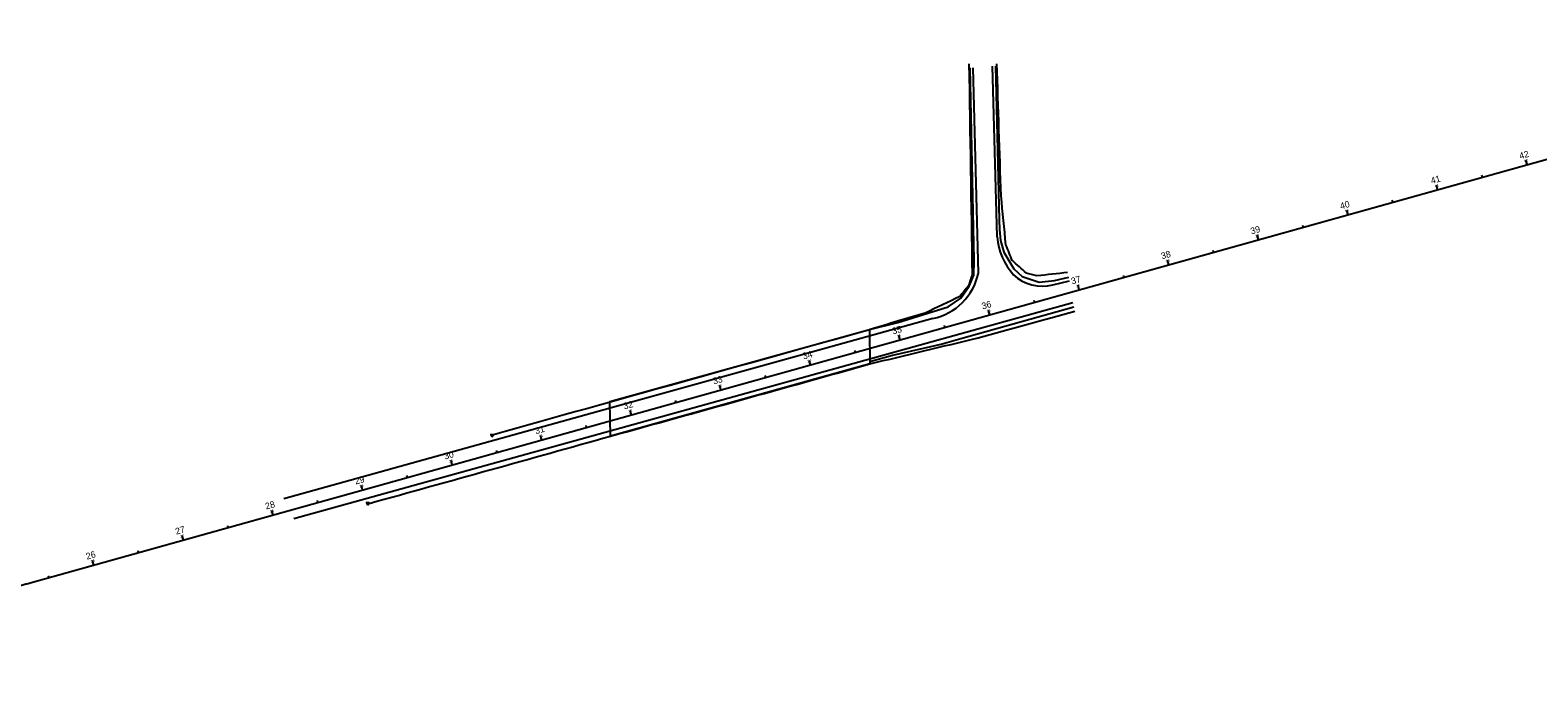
# Model space of a CAD drawing. Extents: x 1512289 to 1610162, y 552531 to 645498.
# Drawn here: x 1541212 to 1542833, y 586720 to 587419 of the extents above; entities that cross this region are included whole.
import ezdxf

# ---------------------------------------------------------------- set-up
doc = ezdxf.new("R2010")
doc.units = 0
for name, color, linetype in [('BR_X_SV_Deck_Top', 7, 'Continuous'), ('GE_X_CL_20', 7, 'Continuous'), ('GE_X_CL_50', 7, 'Continuous'), ('GK_Visualization', 7, 'Continuous'), ('MT_P_CL_Double_Solid', 7, 'Continuous'), ('PV_X_EOP', 7, 'Continuous'), ('PV_X_Shoulder', 7, 'Continuous'), ('RD_X_Anchor_Assembly', 7, 'Continuous'), ('RD_X_GR_Lt', 7, 'Continuous'), ('RD_X_GR_Rt', 7, 'Continuous')]:
    doc.layers.add(name, color=color, linetype=linetype)

msp = doc.modelspace()

# ---------------------------------------------------------------- linework, layer by layer
at = {"layer": 'BR_X_SV_Deck_Top'}
msp.add_lwpolyline([(1541836.1, 586981.9), (1541835.6, 587019.2), (1542114.7, 587096.4), (1542114.9, 587059.6)], close=True, dxfattribs=at)
at = {"layer": 'GE_X_CL_20'}
for p, q in [((1541212.2, 586824.2), (1543339.3, 587418.5)), ((1542821.7, 587273.9), (1542821.2, 587275.8)), ((1542773.6, 587260.4), (1542773, 587262.4)), ((1542725.4, 587247), (1542724.9, 587248.9)), ((1542677.3, 587233.5), (1542676.7, 587235.5)), ((1542581, 587206.6), (1542580.4, 587208.5)), ((1542629.1, 587220.1), (1542628.6, 587222)), ((1542532.8, 587193.2), (1542532.3, 587195.1)), ((1542484.6, 587179.7), (1542484.1, 587181.6)), ((1542436.5, 587166.2), (1542435.9, 587168.2)), ((1542388.3, 587152.8), (1542387.8, 587154.7)), ((1542292, 587125.9), (1542291.5, 587127.8)), ((1542340.2, 587139.3), (1542339.6, 587141.3)), ((1542243.9, 587112.4), (1542243.3, 587114.4)), ((1542195.7, 587099), (1542195.2, 587100.9)), ((1542147.6, 587085.5), (1542147, 587087.4)), ((1542099.4, 587072.1), (1542098.9, 587074)), ((1542003.1, 587045.2), (1542002.5, 587047.1)), ((1542051.2, 587058.6), (1542050.7, 587060.5)), ((1541954.9, 587031.7), (1541954.4, 587033.6)), ((1541906.8, 587018.2), (1541906.2, 587020.2)), ((1541858.6, 587004.8), (1541858.1, 587006.7)), ((1541810.5, 586991.3), (1541809.9, 586993.3)), ((1541714.2, 586964.4), (1541713.6, 586966.3)), ((1541762.3, 586977.9), (1541761.8, 586979.8)), ((1541666, 586951), (1541665.5, 586952.9)), ((1541617.8, 586937.5), (1541617.3, 586939.4)), ((1541569.7, 586924.1), (1541569.1, 586926)), ((1541521.5, 586910.6), (1541521, 586912.5)), ((1541425.2, 586883.7), (1541424.7, 586885.6)), ((1541473.4, 586897.1), (1541472.8, 586899.1)), ((1541377.1, 586870.2), (1541376.5, 586872.2)), ((1541328.9, 586856.8), (1541328.4, 586858.7)), ((1541280.8, 586843.3), (1541280.2, 586845.2)), ((1541232.6, 586829.9), (1541232.1, 586831.8))]:
    msp.add_line(p, q, dxfattribs=at)
at = {"layer": 'GE_X_CL_50'}
for p, q in [((1541212.2, 586824.2), (1543339.3, 587418.5)), ((1542821.7, 587273.9), (1542820.4, 587278.7)), ((1542725.4, 587247), (1542724.1, 587251.8)), ((1542629.1, 587220.1), (1542627.8, 587224.9)), ((1542532.8, 587193.2), (1542531.5, 587198)), ((1542436.5, 587166.2), (1542435.1, 587171.1)), ((1542340.2, 587139.3), (1542338.8, 587144.2)), ((1542243.9, 587112.4), (1542242.5, 587117.2)), ((1542147.6, 587085.5), (1542146.2, 587090.3)), ((1542051.2, 587058.6), (1542049.9, 587063.4)), ((1541954.9, 587031.7), (1541953.6, 587036.5)), ((1541858.6, 587004.8), (1541857.3, 587009.6)), ((1541762.3, 586977.9), (1541761, 586982.7)), ((1541666, 586951), (1541664.7, 586955.8)), ((1541569.7, 586924.1), (1541568.3, 586928.9)), ((1541473.4, 586897.1), (1541472, 586902)), ((1541377.1, 586870.2), (1541375.7, 586875)), ((1541280.8, 586843.3), (1541279.4, 586848.1))]:
    msp.add_line(p, q, dxfattribs=at)
at = {"layer": 'GK_Visualization'}
for p, q in [((1541212.2, 586824.2), (1543339.3, 587418.5)), ((1541212.2, 586824.3), (1541212.2, 586824.1)), ((1541212.3, 586824.2), (1541212.2, 586824.2))]:
    msp.add_line(p, q, dxfattribs=at)
msp.add_spline([(1540878.3, 586719.8), (1540882.7, 586721.5), (1540887.2, 586723.1), (1540891.6, 586724.8), (1540896, 586726.4), (1540900.5, 586728.1), (1540904.9, 586729.7), (1540909.4, 586731.3), (1540913.8, 586732.9), (1540918.3, 586734.5), (1540922.7, 586736.1), (1540927.2, 586737.7), (1540931.6, 586739.2), (1540936.1, 586740.8), (1540940.6, 586742.4), (1540945, 586743.9), (1540949.5, 586745.4), (1540954, 586746.9), (1540958.5, 586748.5), (1540963, 586750), (1540967.4, 586751.5), (1540971.9, 586753), (1540976.4, 586754.4), (1540980.9, 586755.9), (1540985.4, 586757.4), (1540989.9, 586758.8), (1540994.4, 586760.3), (1540998.9, 586761.7), (1541003.4, 586763.2), (1541007.9, 586764.6), (1541012.4, 586766), (1541017, 586767.4), (1541021.5, 586768.8), (1541026, 586770.2), (1541030.5, 586771.6), (1541035, 586773), (1541039.5, 586774.4), (1541044.1, 586775.8), (1541048.6, 586777.2), (1541053.1, 586778.5), (1541057.7, 586779.9), (1541062.2, 586781.3), (1541066.7, 586782.6), (1541071.3, 586784), (1541075.8, 586785.3), (1541080.3, 586786.7), (1541084.9, 586788), (1541089.4, 586789.3), (1541093.9, 586790.6), (1541098.5, 586792), (1541103, 586793.3), (1541107.6, 586794.6), (1541112.1, 586795.9), (1541116.7, 586797.2), (1541121.2, 586798.5), (1541125.7, 586799.8), (1541130.3, 586801.1), (1541134.8, 586802.4), (1541139.4, 586803.7), (1541143.9, 586805), (1541148.5, 586806.3), (1541153, 586807.6), (1541157.6, 586808.9), (1541162.1, 586810.1), (1541166.7, 586811.4), (1541171.3, 586812.7), (1541175.8, 586814), (1541180.4, 586815.3), (1541184.9, 586816.5), (1541189.5, 586817.8), (1541194, 586819.1), (1541198.6, 586820.4), (1541203.1, 586821.6), (1541207.7, 586822.9), (1541212.2, 586824.2)], degree=3, dxfattribs=at)
msp.add_spline([(1540878.3, 586719.8), (1540882.7, 586721.5), (1540887.2, 586723.1), (1540891.6, 586724.8), (1540896, 586726.4), (1540900.5, 586728.1), (1540904.9, 586729.7), (1540909.4, 586731.3), (1540913.8, 586732.9), (1540918.3, 586734.5), (1540922.7, 586736.1), (1540927.2, 586737.7), (1540931.6, 586739.2), (1540936.1, 586740.8), (1540940.6, 586742.4), (1540945, 586743.9), (1540949.5, 586745.4), (1540954, 586746.9), (1540958.5, 586748.5), (1540963, 586750), (1540967.4, 586751.5), (1540971.9, 586753), (1540976.4, 586754.4), (1540980.9, 586755.9), (1540985.4, 586757.4), (1540989.9, 586758.8), (1540994.4, 586760.3), (1540998.9, 586761.7), (1541003.4, 586763.2), (1541007.9, 586764.6), (1541012.4, 586766), (1541017, 586767.4), (1541021.5, 586768.8), (1541026, 586770.2), (1541030.5, 586771.6), (1541035, 586773), (1541039.5, 586774.4), (1541044.1, 586775.8), (1541048.6, 586777.2), (1541053.1, 586778.5), (1541057.7, 586779.9), (1541062.2, 586781.3), (1541066.7, 586782.6), (1541071.3, 586784), (1541075.8, 586785.3), (1541080.3, 586786.7), (1541084.9, 586788), (1541089.4, 586789.3), (1541093.9, 586790.6), (1541098.5, 586792), (1541103, 586793.3), (1541107.6, 586794.6), (1541112.1, 586795.9), (1541116.7, 586797.2), (1541121.2, 586798.5), (1541125.7, 586799.8), (1541130.3, 586801.1), (1541134.8, 586802.4), (1541139.4, 586803.7), (1541143.9, 586805), (1541148.5, 586806.3), (1541153, 586807.6), (1541157.6, 586808.9), (1541162.1, 586810.1), (1541166.7, 586811.4), (1541171.3, 586812.7), (1541175.8, 586814), (1541180.4, 586815.3), (1541184.9, 586816.5), (1541189.5, 586817.8), (1541194, 586819.1), (1541198.6, 586820.4), (1541203.1, 586821.6), (1541207.7, 586822.9), (1541212.2, 586824.2)], degree=3, dxfattribs=at)
at = {"layer": 'MT_P_CL_Double_Solid'}
msp.add_line((1542364.3, 587146), (1542845.8, 587280.6), dxfattribs=at)
at = {"layer": 'PV_X_EOP'}
for p, q in [((1542231.7, 587157.2), (1542226.2, 587378)), ((1542251.7, 587196.1), (1542246.8, 587379.6)), ((1542311.7, 587144.7), (1542329.7, 587148.8)), ((1542333.3, 587125.1), (1541495.6, 586892.8)), ((1542182.7, 587108.4), (1541484.8, 586914.4))]:
    msp.add_line(p, q, dxfattribs=at)
for centre, radius, start, end in [((1542320.3, 587201.9), 68.8, 184.8254, 222.4062), ((1542170.5, 587169.7), 62.4, 281.2139, 348.4506), ((1542300.1, 587187.5), 44.3, 226.2053, 285.2475)]:
    msp.add_arc(centre, radius, start, end, dxfattribs=at)
at = {"layer": 'PV_X_Shoulder'}
for points in [[(1542114.7, 587096.4), (1542145.1, 587104.2), (1542199.3, 587120.8), (1542212.9, 587130.4), (1542221.9, 587143.3), (1542226.7, 587155), (1542227.2, 587171), (1542222.7, 587378)], [(1542250.2, 587379.6), (1542254.2, 587214.6), (1542254.5, 587204), (1542255.4, 587192.2), (1542259, 587179.6), (1542269.9, 587161.7), (1542278.8, 587153.7), (1542297.2, 587147.4), (1542313.5, 587149.3), (1542329, 587152.7)], [(1542334.3, 587120.6), (1542212.7, 587086.7), (1542192.6, 587080.9), (1542139.5, 587068.5), (1542114.9, 587061.9)]]:
    msp.add_lwpolyline(points, dxfattribs=at)
at = {"layer": 'RD_X_Anchor_Assembly'}
for points in [[(1541708.7, 586981.2), (1541710.5, 586983.4), (1541707.6, 586983.8)], [(1541575, 586907.8), (1541576.7, 586910.1), (1541573.9, 586910.4)]]:
    msp.add_lwpolyline(points, close=True, dxfattribs=at)
at = {"layer": 'RD_X_GR_Lt'}
for centre, radius, start, end in [((1534235.2, 616124), 30117.3, 285.39663, 285.60221), ((1534361.7, 619537.7), 33390.7, 283.42641, 283.63199), ((1520328.7, 664721.2), 80659.6, 285.464626, 285.670205), ((1521573.7, 659217.2), 75023.4, 285.463483, 285.669062)]:
    msp.add_arc(centre, radius, start, end, dxfattribs=at)
at = {"layer": 'RD_X_GR_Rt'}
for centre, radius, start, end in [((3234596.3, 612398.8), 1692559.6, 180.8468843, 180.8545504), ((479730.9, 553586.9), 1063058, 1.8141208, 1.8217869), ((1149971.9, 548704), 394172.5, 5.602802, 5.610468), ((1414393.2, 536043.9), 137716.9, 21.792409, 21.800075), ((1442496, 474076.2), 150813.9, 48.573508, 48.581174), ((1627381, 517588.8), 109954.8, 140.759703, 140.76737), ((1633808, 557735.3), 96192.6, 162.190728, 162.198394), ((1519007.3, 501908), 88369.7, 74.720867, 74.728533), ((1569928.3, 341509.6), 247194, 96.410799, 96.418465), ((1675563.6, 307707.1), 309614.3, 115.512201, 115.519867), ((1673944.7, 145678.3), 460683.3, 106.620573, 106.628239), ((1825870.5, -430626.2), 1056539.8, 105.5791754, 105.6020033)]:
    msp.add_arc(centre, radius, start, end, dxfattribs=at)

# ---------------------------------------------------------------- texts
at = {"layer": 'GE_X_CL_20'}
for s, p in [('42', (1542818.7, 587276.2)), ('41', (1542722.9, 587249.4)), ('40', (1542626, 587222.3)), ('39', (1542529.8, 587195.4)), ('38', (1542433.5, 587168.5)), ('37', (1542337.1, 587141.6)), ('36', (1542240.8, 587114.7)), ('35', (1542144.5, 587087.8)), ('34', (1542048.2, 587060.9)), ('33', (1541951.9, 587034)), ('32', (1541855.6, 587007.1)), ('31', (1541759.8, 586980.3)), ('30', (1541662.9, 586953.2)), ('29', (1541566.7, 586926.3)), ('28', (1541470.4, 586899.4)), ('27', (1541374, 586872.5)), ('26', (1541277.8, 586845.6))]:
    msp.add_text(s, height=2.8, rotation=15.6111, dxfattribs=at).set_placement(p)
at = {"layer": 'GE_X_CL_50'}
for s, p in [('42', (1542814.2, 587279.6)), ('41', (1542719.1, 587253)), ('40', (1542621.5, 587225.7)), ('39', (1542525.3, 587198.8)), ('38', (1542429.1, 587172)), ('37', (1542332.4, 587145)), ('36', (1542236.3, 587118.1)), ('35', (1542140, 587091.2)), ('34', (1542043.8, 587064.3)), ('33', (1541947.3, 587037.4)), ('32', (1541851.1, 587010.5)), ('31', (1541755.9, 586983.9)), ('30', (1541658.3, 586956.6)), ('29', (1541562.3, 586929.8)), ('28', (1541466, 586902.9)), ('27', (1541369.4, 586875.9)), ('26', (1541273.3, 586849))]:
    msp.add_text(s, height=7, rotation=15.6111, dxfattribs=at).set_placement(p)

doc.saveas('drawing.dxf')
